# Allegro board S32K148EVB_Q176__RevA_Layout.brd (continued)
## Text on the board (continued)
Ref Des/Silkscreen Top: LIN2 | LIN1 | CAN | L | VBAT | E | F | N | J | VDD | H | G | K | P5V0 | I | SAI AUDIO | VDD_MCU | M | B | VREFH_MCU | VDDA_MCU | A | DEBUG ETM | CORTEX | C | P3V3 | ADC POT | D | VSUP | WK-UP | BTN0 | BTN1 | SW4 | S32K148EVB-Q144 | S32K148EVB-Q176 | 11 OF 14 | PRIMARY SILKSCREEN
L2_GND_1: 2 OF 14 | GROUND PLANE 1
L3_INT_1: 3 OF 14 | INTERNAL 1
L4_PWR_1: 4 OF 14 | POWER PLANE 1
L5_PWR_2: 5 OF 14 | POWER PLANE 2
L6_INT_2: 6 OF 14 | INTERNAL 2
L7_GND_2: 7 OF 14 | GROUND PLANE 2
DIMENSION: 0 | PRIMARY DATUM | GRID ORIGIN
BODY_CENTER: 22. | INTENTIONAL 1 SHORTS AT: | Location           RefDes      Net 1                  Net 2 | (1770.00 -501.00)  J11       SDA_RST_TGTMCU_J_B  &  SDA_RST_TGTMCU_B | 16 | 17 | 8
DISPLAY_TOP: 10 OF 14 | PASTEMASK TOP
User.5: 13 OF 14 | SECONDARY PASTEMASK
User.15: 07-17-17 | 08-09-17 | W.R. | B | C | SCHEMATIC CHANGED | CHANGES PER ECO75024
User.18: L8_SS | 16.00 | 50 | ---- | 9.00 | 5.00 | 90
User.24: FIGURE | SIZE | 10.0 | 15.0 | 28.0 | 31.0 | 40.0 | 44.0 | 45.0 | 47.0 | 63.0 | 100.0 | 125.0 | 34.0x26.0 | 60.0x33.0 | 111.0x32.0 | 122.0x32.0 | DRILL CHART: TOP to BOTTOM | ALL UNITS ARE IN MILS | TOLERANCE | +0.0/-10.0 | +2.0/-2.0 | +3.0/-3.0 | PLATED | NON-PLATED | QTY | 1035 | 2 | 12 | 10 | 183 | 4 | 1 | 50 | 8 | 5 | 3
